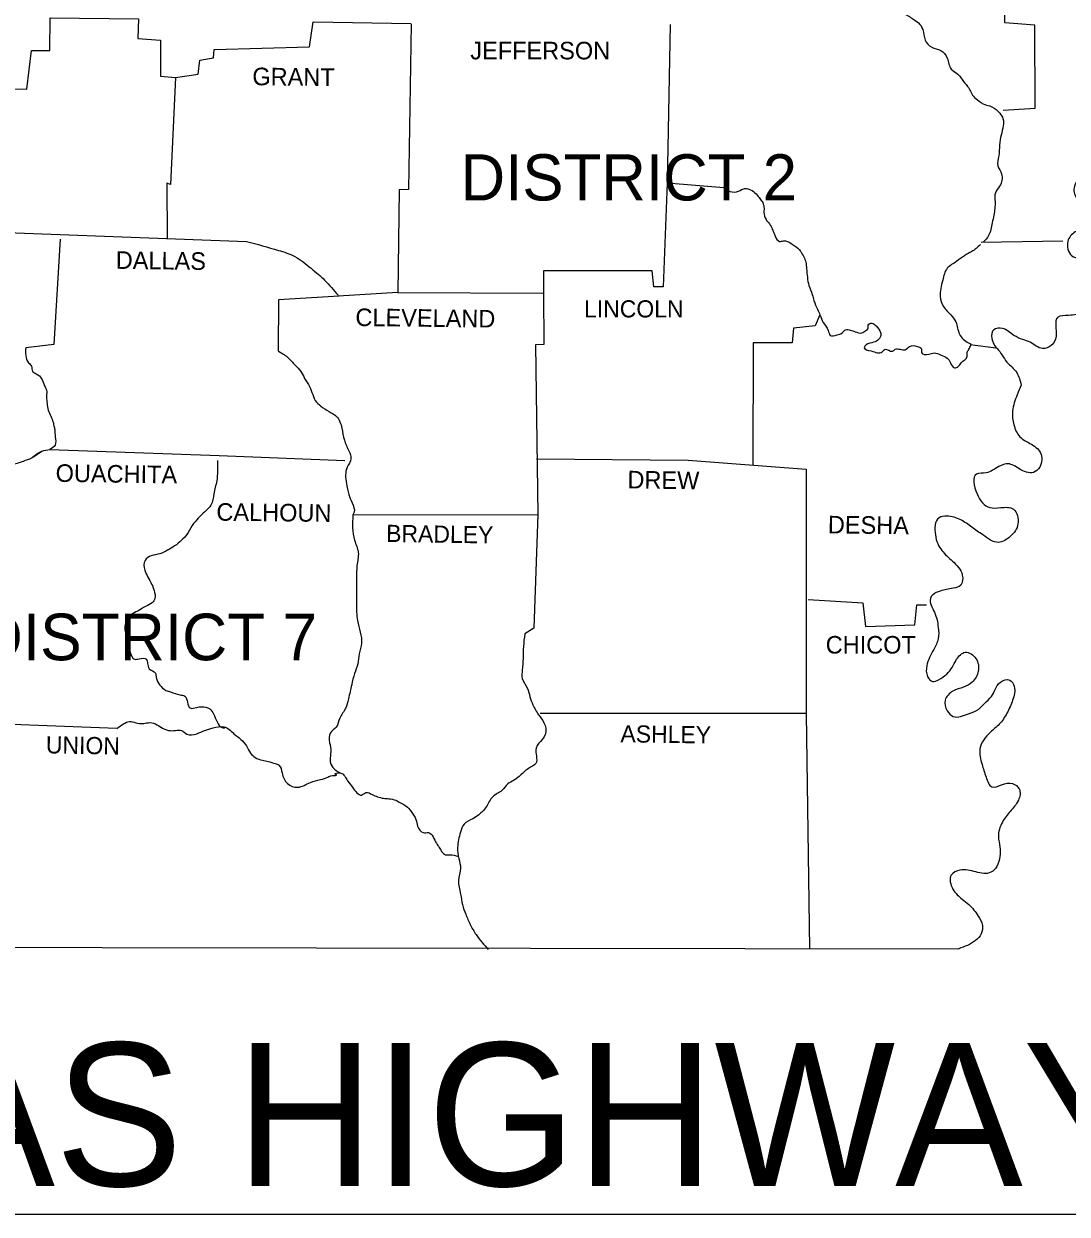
# Model space of a CAD drawing. Extents: x -17742 to 32032, y -17264 to 5867.
# Drawn here: x -16539 to -15135, y 2539 to 4141 of the extents above; entities that cross this region are included whole.
import ezdxf

# ---------------------------------------------------------------- set-up
doc = ezdxf.new("R2010")
doc.units = 0
for name, color, linetype in [('1', 7, 'Continuous'), ('2', 7, 'Continuous'), ('3', 7, 'Continuous')]:
    doc.layers.add(name, color=color, linetype=linetype)

msp = doc.modelspace()

# ---------------------------------------------------------------- linework, layer by layer
at = {"layer": '1'}
for p, q in [((-15250.6, 3847.5), (-15140.6, 3849.1)), ((-17741.9, 2539.3), (-14228.8, 2539.3))]:
    msp.add_line(p, q, dxfattribs=at)
for points in [[(-15220.9, 4025.3), (-15178, 4028), (-15178.6, 4139.7), (-15218.7, 4142.5), (-15216.5, 4361), (-15251.2, 4365.9), (-15252.3, 4512.9), (-14782.8, 4516.2)], [(-16849.4, 4057.7), (-16534.6, 4053.3), (-16528.6, 4105.6), (-16503.8, 4105.6), (-16503.3, 4149.6), (-16384.4, 4148), (-16385.5, 4121.6), (-16354.7, 4119.4), (-16354.7, 4070.9), (-16334.8, 4069.3)], [(-16334.8, 4069.3), (-16304, 4073.7), (-16301.8, 4092.4), (-16283.7, 4095.7), (-16282.6, 4106.7), (-16154.3, 4110.6), (-16149.4, 4144.1), (-16017.8, 4141.9)], [(-16017.8, 4140.8), (-16021.1, 3918.5), (-16033.8, 3917.9), (-16035.5, 3779.8)], [(-15668.9, 4140.3), (-15673.3, 3927.3), (-15596.8, 3921.2)], [(-16334.8, 4069.3), (-16341.4, 3925.1), (-16346.4, 3926.7), (-16345.9, 3851.9)], [(-16901.3, 4011.4), (-16901.2, 4012.6), (-16816.4, 4007.1), (-16818.6, 3963.6), (-16709.1, 3957.6), (-16708.5, 3931.2), (-16609.5, 3925.1), (-16592.4, 3895.4), (-16602.9, 3882.2), (-16597.9, 3861.8), (-16239.1, 3848.6)], [(-15673.3, 3927.3), (-15678.3, 3787.5), (-15690.9, 3787.5), (-15693.1, 3809), (-15839.5, 3809), (-15839.5, 3778.2)], [(-16490, 3851.4), (-16498.3, 3709.9), (-16536.3, 3705.5)], [(-16114.7, 3774.9), (-16196.2, 3769.9), (-16196.7, 3701.1)], [(-16035.5, 3779.8), (-16115.8, 3774.9)], [(-16035.5, 3779.8), (-15840.6, 3778.7)], [(-15839.5, 3778.7), (-15839, 3709.9), (-15850.5, 3709.4), (-15847.2, 3481)], [(-15467.5, 3749.5), (-15474.1, 3734.7), (-15503.3, 3731.9), (-15504.9, 3712.1), (-15557.2, 3712.1), (-15557.7, 3547.6)], [(-16503.8, 3568.5), (-16276, 3560.2), (-16107, 3553.6)], [(-15848.9, 3555.8), (-15644.7, 3554.2), (-15486.2, 3542.1)], [(-15486.2, 3542.1), (-15486.2, 3212.9), (-15481.8, 2896.5)], [(-16096, 3480.4), (-15847.2, 3481)], [(-15847.2, 3481), (-15852.7, 3328), (-15864.8, 3320.3)], [(-15483.4, 3366.5), (-15409.7, 3362.1), (-15406.4, 3330.2), (-15339.8, 3332.4), (-15337.1, 3359.3), (-15324.4, 3359.3)], [(-17299.1, 3345), (-17298, 2899.8), (-15280.9, 2896.5)], [(-16413.5, 3193.1), (-16648.5, 3201.9), (-16649.6, 3257.5)], [(-15843.9, 3213.5), (-15486.2, 3213.5)]]:
    msp.add_lwpolyline(points, dxfattribs=at)
for points in [[(-14817.5, 4383), (-14830.2, 4367), (-14848.9, 4376.9), (-14848.9, 4390.1), (-14846.1, 4403.9), (-14852.7, 4412.7), (-14864.3, 4408.9), (-14864.3, 4391.8), (-14865.4, 4375.3), (-14868.7, 4351.6), (-14861, 4344.5), (-14843.4, 4342.3), (-14830.7, 4339), (-14823, 4326.3), (-14823.6, 4310.9), (-14829.6, 4296), (-14838.4, 4283.9), (-14852.2, 4279.5), (-14863.2, 4286.7), (-14867.6, 4301), (-14872.6, 4313.6), (-14881.9, 4323), (-14891.8, 4312.5), (-14894, 4293.3), (-14893.5, 4276.8), (-14893.5, 4254.2), (-14879.2, 4239.3), (-14870.4, 4222.3), (-14873.1, 4206.9), (-14883.6, 4188.7), (-14888, 4172.8), (-14892.4, 4151.3), (-14891.8, 4127.6), (-14895.7, 4104.5), (-14903.4, 4089.1), (-14917.7, 4076.4), (-14927, 4068.2), (-14934.7, 4059.9), (-14938.6, 4043.4), (-14941.3, 4031.9), (-14951.8, 4018.1), (-14960.1, 4017), (-14966.7, 4022.5), (-14968.9, 4031.9), (-14968.9, 4041.2), (-14973.3, 4050.6), (-14987, 4054.4), (-14998, 4053.9), (-15003, 4046.2), (-14995.8, 4024.7), (-14993.1, 4011), (-14996.9, 3992.2), (-14994.7, 3990), (-15014.5, 3979.6), (-15030.5, 3977.9), (-15043.7, 3974.1), (-15056.4, 3965.8), (-15062.4, 3953.7), (-15071.2, 3943.8), (-15078.9, 3934.5), (-15089.4, 3930.1), (-15101, 3932.3), (-15116.4, 3933.9), (-15125.2, 3922.9), (-15122.4, 3906.9), (-15112, 3897.6), (-15096.5, 3893.2), (-15080.6, 3894.3), (-15065.2, 3895.9), (-15050.9, 3888.2), (-15053.6, 3873.4), (-15067.4, 3866.2), (-15087.7, 3864), (-15104.3, 3865.7), (-15124.1, 3861.3), (-15134, 3848.6), (-15128.5, 3829.3), (-15107, 3821.6), (-15097.1, 3803.5), (-15096.5, 3786.4), (-15103.7, 3763.8), (-15113.6, 3753.4), (-15132.9, 3749), (-15147.7, 3746.2), (-15149.9, 3720.9), (-15156.5, 3708.3), (-15168.1, 3704.4), (-15184.6, 3712.7), (-15194.5, 3716.5), (-15206.6, 3722), (-15222, 3731.4), (-15233.6, 3729.7), (-15230.3, 3705.5), (-15229.2, 3704.4), (-15216, 3686.2), (-15202.8, 3671.9), (-15196.7, 3654.9)], [(-15387.7, 4205.8), (-15386, 4183.2), (-15372.8, 4179.9), (-15367.3, 4173.9), (-15364.6, 4161.2), (-15355.2, 4155.7), (-15342.6, 4148), (-15334.9, 4142.5), (-15329.3, 4133.7), (-15326, 4119.4), (-15317.2, 4110), (-15305.1, 4105.6), (-15296.3, 4095.2), (-15290.8, 4080.3), (-15282, 4073.7), (-15273.2, 4062.1), (-15268.8, 4057.2), (-15261.1, 4044), (-15253.4, 4037.4), (-15247.9, 4033.5), (-15239.1, 4030.8), (-15228.1, 4023.6), (-15220.9, 4012.6), (-15220.9, 4004.3), (-15223.7, 3991.7), (-15225.9, 3978.5), (-15227, 3963.6), (-15228.1, 3950.4), (-15223.1, 3939.4), (-15225.9, 3922.9), (-15231.4, 3914.1), (-15231.9, 3902), (-15233.6, 3883.8), (-15235.8, 3873.4), (-15240.7, 3856.3), (-15247.9, 3847.5)], [(-15596.8, 3921.2), (-15588.6, 3915.7), (-15577, 3916.3), (-15569.3, 3919.6), (-15563.2, 3919), (-15555, 3914.1), (-15549.5, 3907.5), (-15545.6, 3902.5), (-15542.9, 3894.8), (-15542.9, 3887.7), (-15540.1, 3877.8), (-15536.8, 3873.9), (-15532.4, 3866.8), (-15529.7, 3860.2), (-15528, 3855.8), (-15522, 3848.6), (-15516.5, 3849.1), (-15511.5, 3848.6), (-15504.9, 3844.7), (-15495, 3837), (-15493.4, 3834.8), (-15486.7, 3820.5), (-15485.6, 3811.7), (-15484.5, 3800.2), (-15482.3, 3789.2), (-15477.9, 3777.1), (-15475.7, 3768.8), (-15470.8, 3757.2), (-15467.5, 3749.5), (-15463.1, 3739.6), (-15456.5, 3728.6), (-15453.7, 3722), (-15444.4, 3722.6), (-15437.8, 3725.3), (-15432.8, 3729.7), (-15426.8, 3729.2), (-15420.2, 3727), (-15411.4, 3725.3), (-15405.8, 3728.6), (-15403.1, 3730.8), (-15402.5, 3735.8), (-15397.6, 3738.5), (-15392.1, 3734.7), (-15386, 3725.9), (-15386, 3720.4), (-15388.2, 3717.1), (-15395.4, 3712.7), (-15405.3, 3709.4), (-15408, 3705.5), (-15398.7, 3701.1), (-15383.8, 3700), (-15380, 3703.3), (-15370.1, 3700.6), (-15366.2, 3703.3), (-15353, 3702.8), (-15347, 3707.2), (-15334.9, 3706.6), (-15331, 3703.9), (-15331, 3698.9), (-15321.1, 3696.7), (-15313.9, 3698.4), (-15304.6, 3695.6), (-15296.3, 3691.2), (-15291.9, 3685.1), (-15286.4, 3678.5), (-15281.5, 3680.2), (-15277.6, 3685.1), (-15269.4, 3693.9), (-15269.4, 3699.5), (-15267.2, 3703.3), (-15264.4, 3708.8)], [(-16239.1, 3848.6), (-16196.2, 3836.5), (-16174.1, 3828.2), (-16152.1, 3812.3), (-16134, 3796.3), (-16115.8, 3776)], [(-15251.7, 3844.2), (-15263.3, 3834.8), (-15273.2, 3829.3), (-15283.7, 3821.6), (-15296.3, 3812.3), (-15302.4, 3796.3), (-15305.7, 3774.3), (-15301.3, 3761.1), (-15291.4, 3749.5), (-15284.8, 3740.2), (-15279.8, 3723.7), (-15267.7, 3712.1), (-15263.9, 3710.5)], [(-16536.3, 3705.5), (-16536.3, 3695), (-16532.4, 3685.1), (-16528.6, 3680.7), (-16526.9, 3673.6), (-16522, 3670.3), (-16514.8, 3663.7), (-16511, 3654.3), (-16508.2, 3648.3), (-16508.2, 3640.6), (-16507.7, 3632.9), (-16506.6, 3623.5), (-16500, 3607), (-16498.3, 3600.4), (-16497.2, 3594.9), (-16496.6, 3585.5), (-16496.6, 3574.5), (-16503.8, 3568.5)], [(-16196.7, 3701.1), (-16184, 3692.8), (-16173.6, 3681.8), (-16165.9, 3673.6), (-16160.9, 3664.2), (-16154.3, 3653.2), (-16145, 3632.3), (-16136.7, 3625.2), (-16125.2, 3618), (-16118, 3613), (-16110.9, 3597.1), (-16107.5, 3581.1), (-16101.5, 3566.8), (-16098.7, 3555.8), (-16103.7, 3544.8), (-16104.8, 3522.8), (-16101.5, 3507.9), (-16097.1, 3496.9), (-16094.3, 3484.3), (-16096, 3480.4)], [(-15196.7, 3654.9), (-15202.2, 3642.2), (-15208.3, 3620.2), (-15206.6, 3601.5), (-15198.4, 3585.5), (-15185.2, 3576.7), (-15170.8, 3564.1), (-15171.9, 3544.8), (-15180.2, 3537.6), (-15199.5, 3542.6), (-15214.3, 3549.2), (-15227, 3545.4), (-15244, 3537.1), (-15256.7, 3535.4), (-15256.2, 3509), (-15239.1, 3490.3), (-15224.2, 3490.3), (-15207.2, 3488.1), (-15201.1, 3468.3), (-15211, 3451.8), (-15227.5, 3443.5), (-15248.4, 3453.4), (-15263.3, 3463.9), (-15278.2, 3473.8), (-15296.9, 3478.8), (-15307.3, 3476.6), (-15312.3, 3453.4), (-15303.5, 3432.5), (-15289.2, 3418.2), (-15276, 3399.5), (-15278.2, 3385.8), (-15288.1, 3381.9), (-15305.7, 3378), (-15316.1, 3372.5), (-15318.9, 3368.1), (-15313.4, 3349.4), (-15308.4, 3329.1), (-15308.4, 3313.7), (-15314.5, 3299.3), (-15323.8, 3277.3), (-15322.7, 3263), (-15316.1, 3256.4), (-15307.9, 3258.6), (-15296.9, 3266.3), (-15289.7, 3275.1), (-15283.7, 3286.1), (-15272.1, 3295.5), (-15257.8, 3287.2), (-15254.5, 3270.2), (-15262.8, 3255.3), (-15274.3, 3248.7), (-15288.6, 3243.2), (-15299.1, 3231.1), (-15296.3, 3216.8), (-15288.1, 3209.1), (-15267.7, 3212.9), (-15253.9, 3219), (-15246.2, 3226.7), (-15236.9, 3236.1), (-15231.9, 3245.4), (-15224.8, 3255.3), (-15212.1, 3258.1), (-15206.1, 3249.8), (-15208.3, 3231.1), (-15216, 3213.5), (-15226.4, 3198.6), (-15238, 3188.2), (-15252.3, 3165.6), (-15249.5, 3144.7), (-15244, 3127.6), (-15236.3, 3114.4), (-15223.1, 3117.2), (-15208.3, 3118.8), (-15199.5, 3111.7), (-15200.6, 3096.3), (-15211.6, 3081.4), (-15222, 3067.1), (-15227.5, 3047.3), (-15225.3, 3033.5), (-15225.3, 3020.9), (-15229.7, 3007.1), (-15237.4, 2999.4), (-15257.8, 3000), (-15279.3, 3002.2), (-15290.8, 2995.6), (-15288.6, 2976.8), (-15276, 2963.1), (-15267.2, 2955.9), (-15254.5, 2940.5), (-15249, 2927.9), (-15250.6, 2916.8), (-15258.4, 2907.5), (-15280.9, 2896.5)], [(-16514.3, 3566.3), (-16528.6, 3556.9), (-16539.6, 3552.5), (-16547.8, 3549.8), (-16555.5, 3547.6), (-16565.4, 3541), (-16573.1, 3535.4), (-16583.6, 3530.5), (-16593.5, 3527.2), (-16605.6, 3531), (-16612.2, 3534.9), (-16619.4, 3537.6), (-16642.5, 3537.6)], [(-16528.6, 3556.9), (-16514.3, 3566.3), (-16503.8, 3568.5)], [(-16278.2, 3553.6), (-16279.3, 3526.1), (-16283.1, 3509), (-16287, 3493.6), (-16295.2, 3484.8), (-16304, 3476), (-16312.3, 3466.1), (-16319.4, 3454), (-16326.6, 3446.3), (-16335.9, 3438.6), (-16345.3, 3433.1), (-16355.8, 3428.1), (-16367.3, 3425.4), (-16375.6, 3419.3), (-16376.1, 3406.1), (-16366.8, 3387.4), (-16363.5, 3378.6), (-16362.4, 3368.1), (-16366.2, 3362.1), (-16375, 3357.1), (-16385.5, 3351.1), (-16394.8, 3345.6), (-16401.4, 3336.2), (-16402.5, 3323.6), (-16398.1, 3308.7), (-16396.5, 3299.9), (-16389.3, 3286.1), (-16383.8, 3286.7), (-16373.9, 3286.1), (-16372.8, 3283.4), (-16372.3, 3280.6), (-16370.1, 3273.5), (-16361.8, 3267.4), (-16360.7, 3261.9), (-16355.8, 3251.5), (-16347.5, 3244.3), (-16341.4, 3242.1), (-16328.8, 3238.3), (-16322.2, 3236.6), (-16315, 3220.6), (-16306.2, 3221.2), (-16299.6, 3222.3), (-16288.6, 3219.5), (-16283.7, 3212.9), (-16278.7, 3201.9), (-16272.1, 3194.2), (-16267.7, 3194.2)], [(-16096, 3480.4), (-16093.8, 3446.3), (-16088.8, 3429.8), (-16090.5, 3412.2), (-16091, 3395.1), (-16091, 3379.7), (-16091, 3364.8), (-16091, 3349.4), (-16089.9, 3338.4), (-16086.1, 3322.5), (-16084.4, 3307.6), (-16087.7, 3293.3), (-16089.4, 3280.1), (-16093.8, 3266.9), (-16097.6, 3252), (-16102, 3232.8), (-16105.9, 3220.1), (-16113.6, 3206.9), (-16118.6, 3194.8), (-16126.3, 3187.1), (-16127.4, 3173.9), (-16125.7, 3161.8), (-16126.8, 3150.7), (-16123, 3140.3), (-16113.1, 3133.1)], [(-15864.8, 3320.3), (-15866.5, 3303.2), (-15867, 3287.2), (-15868.1, 3271.8), (-15868.1, 3260.3), (-15861.5, 3247.6), (-15857.7, 3235.5), (-15853.8, 3225), (-15846.1, 3211.3), (-15839, 3200.8), (-15836.8, 3186), (-15841.2, 3178.3), (-15849.4, 3166.7), (-15850, 3145.8), (-15859.9, 3139.2), (-15872.5, 3128.2), (-15879.7, 3123.2), (-15887.4, 3118.3), (-15895.7, 3109.5), (-15907.8, 3101.2), (-15916.6, 3087.5), (-15926.5, 3077), (-15934.7, 3071.5), (-15946.3, 3064.3), (-15951.2, 3053.3), (-15955.1, 3033), (-15953.4, 3018.1), (-15951.2, 3004.9), (-15954, 2988.4), (-15951.2, 2970.2), (-15948.5, 2955.9), (-15944.1, 2943.3), (-15938, 2929), (-15930.3, 2915.7), (-15913.8, 2895.4)], [(-16413.5, 3193.1), (-16404.7, 3199.2), (-16396.5, 3202.5), (-16388.2, 3200.8), (-16379.4, 3199.7), (-16371.7, 3200.8), (-16361.8, 3199.2), (-16353.6, 3194.2), (-16344.2, 3190.4), (-16334.8, 3190.4), (-16326.6, 3190.4), (-16319.4, 3185.4), (-16306.2, 3186), (-16295.2, 3190.4), (-16284.2, 3193.7), (-16269.4, 3195.3), (-16256.1, 3186), (-16246.8, 3178.3), (-16239.1, 3169.5), (-16233.6, 3159.6), (-16227.5, 3154.1), (-16217.6, 3150.2), (-16209.9, 3148.5), (-16200.6, 3145.8), (-16195.6, 3143.6), (-16191.2, 3133.1), (-16184, 3118.8), (-16170.3, 3113.9), (-16153.2, 3120.5), (-16139.5, 3124.3), (-16129.6, 3127.6), (-16123.5, 3129.8), (-16118, 3130.4), (-16119.7, 3131.5), (-16113.1, 3133.1), (-16107, 3128.7), (-16103.1, 3122.7), (-16096.5, 3113.9), (-16090.5, 3106.2), (-16084.4, 3103.4), (-16078.4, 3106.7), (-16070.1, 3104), (-16063, 3101.2), (-16054.7, 3099), (-16047.6, 3098.5), (-16038.2, 3096.3), (-16031, 3092.4), (-16024.4, 3088.6), (-16017.8, 3081.4), (-16011.2, 3070.4), (-16009, 3061.6), (-16001.3, 3052.8), (-15994.2, 3052.8), (-15983.7, 3038.5), (-15979.9, 3033), (-15971.6, 3023.1), (-15965.6, 3023.1), (-15954, 3020.9)]]:
    msp.add_spline(points, degree=3, dxfattribs=at)
at = {"layer": '3'}
msp.add_line((-15265.5, 3709.9), (-15230.8, 3705.5), dxfattribs=at)

# ---------------------------------------------------------------- texts
at = {"layer": '2'}
for s, height, p in [('JEFFERSON', 23.67, (-15938, 4093.5)), ('LINCOLN', 23.11, (-15785, 3746.2)), ('CHICOT', 23.67, (-15459.8, 3293.8)), ('ARKANSAS HIGHWAY DISTRICT 3', 192.623, (-17727.9, 2577.3))]:
    msp.add_text(s, height=height, dxfattribs=at).set_placement(p)
for s, height, rotation, p in [('GRANT', 23.67, 359.4032, (-16231.4, 4058.8)), ('DALLAS', 23.66, 359.2462, (-16415.2, 3811.7)), ('CLEVELAND', 23.67, 359.3377, (-16092.7, 3734.7)), ('OUACHITA', 23.67, 359.2043, (-16496.1, 3525)), ('DREW', 23.66, 359.2258, (-15726.7, 3516.2)), ('CALHOUN', 23.67, 359.3634, (-16279.8, 3472.7)), ('DESHA', 23.66, 359.3704, (-15457, 3455.6)), ('BRADLEY', 23.11, 359.1449, (-16051.4, 3444.1)), ('ASHLEY', 23.11, 359.2361, (-15736.1, 3174.4)), ('UNION', 23.11, 358.9584, (-16509.3, 3159.6))]:
    msp.add_text(s, height=height, rotation=rotation, dxfattribs=at).set_placement(p)
at = {"layer": '3'}
for s, height, p in [('DISTRICT 2', 62.19, (-15951.2, 3903.6)), ('DISTRICT 7', 62.74, (-16600.8, 3284.8))]:
    msp.add_text(s, height=height, dxfattribs=at).set_placement(p)

doc.saveas('drawing.dxf')
